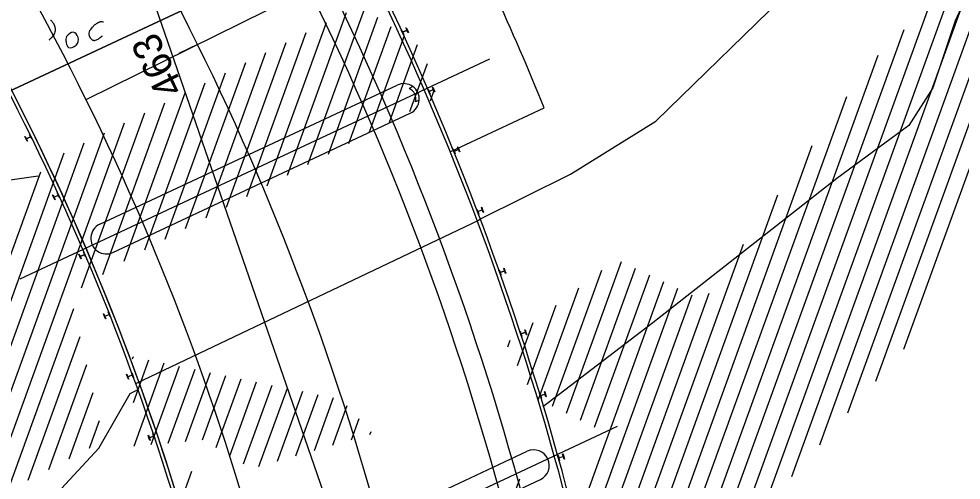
# Model space of a CAD drawing. Extents: x 2355002 to 2355569, y 708374 to 709566.
# Drawn here: x 2355318.9 to 2355409.8, y 709300.1 to 709344.6 of the extents above; entities that cross this region are included whole.
import ezdxf

# ---------------------------------------------------------------- set-up
doc = ezdxf.new("R2010")
doc.units = 0
for name, color, linetype in [('BD_X_Building', 7, 'Continuous'), ('BR_X_Brg_Centerline', 7, 'Continuous'), ('BR_X_Det_Centerline', 7, 'Continuous'), ('BR_X_Rail_Stl_Det', 7, 'Continuous'), ('BR_X_Slab_Object', 7, 'Continuous'), ('DR_X_Ditch', 7, 'Continuous'), ('HY_X_Water_Edge', 7, 'Continuous'), ('HY_X_Wetland_Area', 7, 'Continuous'), ('PM_X_CL_Double_Solid', 7, 'Continuous'), ('PM_X_Edge_Line', 7, 'Continuous'), ('PM_X_Stop_Line', 7, 'Continuous'), ('RD_X_RR_2', 7, 'Continuous'), ('RD_X_RR_Cells', 7, 'Continuous'), ('RD_X_Wall', 7, 'Continuous'), ('VG_X_Cells', 7, 'Continuous'), ('VG_X_Tree_Line_Rt', 7, 'Continuous')]:
    doc.layers.add(name, color=color, linetype=linetype)

msp = doc.modelspace()

# ---------------------------------------------------------------- linework, layer by layer
at = {"layer": 'BD_X_Building'}
msp.add_line((2355325.355, 709336.796), (2355346.875, 709347.42), dxfattribs=at)
msp.add_arc((2355104.75, 709227.886), 272.024, 5.4603, 29.69206, dxfattribs=at)
at = {"layer": 'BR_X_Brg_Centerline'}
for p, q in [((2355319.014, 709319.52), (2355364.3, 709340.715)), ((2355331.329, 709284.107), (2355376.615, 709305.301))]:
    msp.add_line(p, q, dxfattribs=at)
at = {"layer": 'BR_X_Det_Centerline'}
msp.add_line((2355360.141, 709264.65), (2355328.268, 709356.793), dxfattribs=at)
at = {"layer": 'BR_X_Rail_Stl_Det'}
for points in [[(2355356.299, 709343.513), (2355356.211, 709343.704), (2355356.245, 709343.72), (2355356.351, 709343.49)], [(2355355.921, 709343.244), (2355356.008, 709343.053), (2355355.974, 709343.037), (2355355.762, 709343.498), (2355355.797, 709343.514), (2355355.885, 709343.323)], [(2355355.924, 709343.308), (2355356.284, 709343.473)], [(2355356.295, 709343.449), (2355355.935, 709343.284)], [(2355356.351, 709343.49), (2355356.457, 709343.259), (2355356.423, 709343.244), (2355356.335, 709343.435)], [(2355358.465, 709337.535), (2355358.548, 709337.342), (2355358.514, 709337.327), (2355358.313, 709337.792), (2355358.347, 709337.807), (2355358.431, 709337.614)], [(2355358.47, 709337.598), (2355358.834, 709337.756)], [(2355358.844, 709337.731), (2355358.481, 709337.574)], [(2355358.849, 709337.795), (2355358.766, 709337.988), (2355358.801, 709338.003), (2355358.901, 709337.77)], [(2355358.901, 709337.77), (2355359.002, 709337.538), (2355358.967, 709337.523), (2355358.883, 709337.716)], [(2355319.573, 709332.995), (2355319.462, 709333.222), (2355319.496, 709333.239), (2355319.588, 709333.05)], [(2355319.626, 709332.973), (2355319.719, 709332.784), (2355319.685, 709332.767), (2355319.573, 709332.995)], [(2355319.628, 709333.037), (2355319.984, 709333.211)], [(2355319.996, 709333.187), (2355319.64, 709333.013)], [(2355319.998, 709333.251), (2355319.906, 709333.439), (2355319.94, 709333.456), (2355320.162, 709333.001), (2355320.128, 709332.984), (2355320.036, 709333.173)], [(2355360.88, 709331.769), (2355360.959, 709331.575), (2355360.924, 709331.56), (2355360.733, 709332.03), (2355360.768, 709332.044), (2355360.847, 709331.849)], [(2355360.886, 709331.833), (2355361.253, 709331.982)], [(2355361.263, 709331.957), (2355360.896, 709331.808)], [(2355361.27, 709332.021), (2355361.191, 709332.215), (2355361.226, 709332.23), (2355361.321, 709331.995)], [(2355361.321, 709331.995), (2355361.416, 709331.76), (2355361.381, 709331.746), (2355361.302, 709331.941)], [(2355322.241, 709327.358), (2355322.135, 709327.589), (2355322.17, 709327.604), (2355322.257, 709327.413)], [(2355322.293, 709327.335), (2355322.381, 709327.144), (2355322.346, 709327.128), (2355322.241, 709327.358)], [(2355322.297, 709327.398), (2355322.657, 709327.563)], [(2355322.668, 709327.539), (2355322.308, 709327.374)], [(2355322.672, 709327.603), (2355322.584, 709327.794), (2355322.619, 709327.81), (2355322.83, 709327.349), (2355322.795, 709327.333), (2355322.708, 709327.524)], [(2355363.56, 709326.194), (2355363.485, 709326.39), (2355363.521, 709326.403), (2355363.611, 709326.167)], [(2355363.164, 709325.951), (2355363.239, 709325.755), (2355363.203, 709325.741), (2355363.024, 709326.215), (2355363.059, 709326.228), (2355363.134, 709326.032)], [(2355363.172, 709326.014), (2355363.543, 709326.155)], [(2355363.552, 709326.13), (2355363.182, 709325.99)], [(2355363.611, 709326.167), (2355363.701, 709325.93), (2355363.665, 709325.916), (2355363.59, 709326.113)], [(2355324.76, 709321.654), (2355324.661, 709321.887), (2355324.696, 709321.902), (2355324.778, 709321.708)], [(2355324.817, 709321.693), (2355325.182, 709321.848)], [(2355325.192, 709321.823), (2355324.828, 709321.668)], [(2355325.198, 709321.887), (2355325.115, 709322.08), (2355325.15, 709322.095), (2355325.349, 709321.629), (2355325.314, 709321.614), (2355325.231, 709321.808)], [(2355324.812, 709321.629), (2355324.894, 709321.436), (2355324.86, 709321.421), (2355324.76, 709321.654)], [(2355365.315, 709320.082), (2355365.385, 709319.884), (2355365.349, 709319.871), (2355365.18, 709320.349), (2355365.216, 709320.361), (2355365.286, 709320.163)], [(2355365.324, 709320.145), (2355365.698, 709320.277)], [(2355365.707, 709320.252), (2355365.333, 709320.12)], [(2355365.716, 709320.315), (2355365.646, 709320.514), (2355365.681, 709320.526), (2355365.766, 709320.287)], [(2355365.766, 709320.287), (2355365.85, 709320.049), (2355365.815, 709320.036), (2355365.745, 709320.234)], [(2355327.573, 709316.108), (2355327.496, 709316.303), (2355327.531, 709316.317), (2355327.718, 709315.846), (2355327.683, 709315.832), (2355327.605, 709316.027)], [(2355327.13, 709315.886), (2355327.037, 709316.121), (2355327.072, 709316.135), (2355327.15, 709315.94)], [(2355327.181, 709315.86), (2355327.259, 709315.664), (2355327.223, 709315.65), (2355327.13, 709315.886)], [(2355327.188, 709315.923), (2355327.557, 709316.069)], [(2355327.567, 709316.044), (2355327.198, 709315.898)], [(2355367.333, 709314.166), (2355367.399, 709313.967), (2355367.363, 709313.955), (2355367.204, 709314.436), (2355367.24, 709314.448), (2355367.306, 709314.248)], [(2355367.739, 709314.391), (2355367.673, 709314.591), (2355367.709, 709314.603), (2355367.788, 709314.362)], [(2355367.344, 709314.229), (2355367.72, 709314.353)], [(2355367.728, 709314.328), (2355367.352, 709314.204)], [(2355367.788, 709314.362), (2355367.868, 709314.121), (2355367.832, 709314.11), (2355367.766, 709314.309)], [(2355329.349, 709310.058), (2355329.262, 709310.296), (2355329.298, 709310.309), (2355329.37, 709310.111)], [(2355329.399, 709310.03), (2355329.472, 709309.833), (2355329.436, 709309.82), (2355329.349, 709310.058)], [(2355329.408, 709310.094), (2355329.78, 709310.23)], [(2355329.789, 709310.205), (2355329.417, 709310.069)], [(2355329.798, 709310.268), (2355329.726, 709310.465), (2355329.761, 709310.478), (2355329.935, 709310.003), (2355329.9, 709309.99), (2355329.827, 709310.187)], [(2355369.218, 709308.206), (2355369.279, 709308.005), (2355369.242, 709307.994), (2355369.095, 709308.479), (2355369.131, 709308.49), (2355369.192, 709308.289)], [(2355369.23, 709308.269), (2355369.609, 709308.384)], [(2355369.617, 709308.358), (2355369.237, 709308.243)], [(2355369.629, 709308.421), (2355369.567, 709308.622), (2355369.604, 709308.633), (2355369.677, 709308.391)], [(2355369.677, 709308.391), (2355369.751, 709308.149), (2355369.715, 709308.138), (2355369.654, 709308.339)], [(2355331.869, 709304.372), (2355331.802, 709304.572), (2355331.838, 709304.584), (2355332, 709304.104), (2355331.964, 709304.092), (2355331.897, 709304.291)], [(2355331.415, 709304.174), (2355331.334, 709304.414), (2355331.37, 709304.426), (2355331.437, 709304.227)], [(2355331.465, 709304.145), (2355331.532, 709303.946), (2355331.496, 709303.934), (2355331.415, 709304.174)], [(2355331.475, 709304.208), (2355331.85, 709304.335)], [(2355331.859, 709304.309), (2355331.483, 709304.183)], [(2355371.382, 709302.411), (2355371.325, 709302.613), (2355371.362, 709302.623), (2355371.43, 709302.379)], [(2355370.966, 709302.205), (2355371.022, 709302.002), (2355370.986, 709301.992), (2355370.849, 709302.48), (2355370.886, 709302.49), (2355370.943, 709302.288)], [(2355370.979, 709302.267), (2355371.361, 709302.374)], [(2355371.368, 709302.348), (2355370.986, 709302.242)], [(2355371.43, 709302.379), (2355371.498, 709302.135), (2355371.461, 709302.125), (2355371.405, 709302.327)]]:
    msp.add_lwpolyline(points, dxfattribs=at)
for centre, radius, start, end in [((2355104.75, 709227.887), 276.024, 8.80517, 29.69195), ((2355104.75, 709227.887), 276.024, 8.80517, 29.69195), ((2355104.75, 709227.887), 276.357, 8.80517, 29.69195), ((2355104.75, 709227.887), 239.69, 6.23645, 29.69194), ((2355104.75, 709227.887), 240.024, 6.23645, 29.69194), ((2355355.912, 709343.335), 0.0298, 204.67725, 294.67725), ((2355355.948, 709343.257), 0.0298, 114.67725, 204.67725), ((2355356.272, 709343.501), 0.0298, 294.67725, 24.67725), ((2355356.308, 709343.422), 0.0298, 24.67725, 114.67725), ((2355358.458, 709337.626), 0.0298, 203.38147, 293.38147), ((2355358.492, 709337.547), 0.0298, 113.38147, 203.38147), ((2355358.822, 709337.783), 0.0298, 293.38147, 23.38147), ((2355358.856, 709337.704), 0.0298, 23.38147, 113.38147), ((2355319.615, 709333.063), 0.0298, 206.07139, 296.07139), ((2355319.653, 709332.986), 0.0298, 116.07139, 206.07139), ((2355319.971, 709333.237), 0.0298, 296.07139, 26.07139), ((2355320.009, 709333.16), 0.0298, 26.07139, 116.07139), ((2355360.875, 709331.86), 0.0298, 202.08568, 292.08568), ((2355360.907, 709331.781), 0.0298, 112.08568, 202.08568), ((2355361.242, 709332.009), 0.0298, 292.08568, 22.08568), ((2355361.274, 709331.93), 0.0298, 22.08568, 112.08568), ((2355322.284, 709327.426), 0.0298, 204.57738, 294.57738), ((2355322.32, 709327.347), 0.0298, 114.57738, 204.57738), ((2355322.645, 709327.59), 0.0298, 294.57738, 24.57738), ((2355322.681, 709327.512), 0.0298, 24.57738, 114.57738), ((2355363.162, 709326.042), 0.0298, 200.7899, 290.7899), ((2355363.192, 709325.962), 0.0298, 110.7899, 200.7899), ((2355363.532, 709326.183), 0.0298, 290.7899, 20.7899), ((2355363.563, 709326.102), 0.0298, 20.7899, 110.7899), ((2355324.806, 709321.72), 0.0298, 203.08337, 293.08337), ((2355325.17, 709321.875), 0.0298, 293.08337, 23.08337), ((2355325.204, 709321.796), 0.0298, 23.08337, 113.08337), ((2355324.839, 709321.641), 0.0298, 113.08337, 203.08337), ((2355365.314, 709320.173), 0.0298, 199.49411, 289.49411), ((2355365.343, 709320.092), 0.0298, 109.49411, 199.49411), ((2355365.688, 709320.305), 0.0298, 289.49411, 19.49411), ((2355365.716, 709320.224), 0.0298, 19.49411, 109.49411), ((2355327.177, 709315.951), 0.0298, 201.58937, 291.58937), ((2355327.209, 709315.871), 0.0298, 111.58937, 201.58937), ((2355327.546, 709316.097), 0.0298, 291.58937, 21.58937), ((2355327.577, 709316.016), 0.0298, 21.58937, 111.58937), ((2355367.334, 709314.257), 0.0298, 198.28804, 288.28804), ((2355367.361, 709314.175), 0.0298, 108.28804, 198.28804), ((2355367.711, 709314.382), 0.0298, 288.28804, 18.28804), ((2355367.738, 709314.3), 0.0298, 18.28804, 108.28804), ((2355329.398, 709310.122), 0.0298, 200.09536, 290.09536), ((2355329.427, 709310.041), 0.0298, 110.09536, 200.09536), ((2355329.77, 709310.258), 0.0298, 290.09536, 20.09536), ((2355329.799, 709310.177), 0.0298, 20.09536, 110.09536), ((2355369.221, 709308.297), 0.0298, 196.90255, 286.90255), ((2355369.246, 709308.215), 0.0298, 106.90255, 196.90255), ((2355369.6, 709308.412), 0.0298, 286.90255, 16.90255), ((2355369.625, 709308.33), 0.0298, 16.90255, 106.90255), ((2355331.465, 709304.237), 0.0298, 198.60135, 288.60135), ((2355331.493, 709304.155), 0.0298, 108.60135, 198.60135), ((2355331.841, 709304.363), 0.0298, 288.60135, 18.60135), ((2355331.868, 709304.281), 0.0298, 18.60135, 108.60135), ((2355370.971, 709302.296), 0.0298, 195.60676, 285.60676), ((2355370.994, 709302.213), 0.0298, 105.60676, 195.60676), ((2355371.353, 709302.403), 0.0298, 285.60676, 15.60676), ((2355371.376, 709302.319), 0.0298, 15.60676, 105.60676)]:
    msp.add_arc(centre, radius, start, end, dxfattribs=at)
at = {"layer": 'BR_X_Slab_Object'}
msp.add_arc((2355104.75, 709227.887), 240.024, 6.69347, 29.69206, dxfattribs=at)
at = {"layer": 'DR_X_Ditch'}
msp.add_lwpolyline([(2355256.934, 709256.527), (2355268.599, 709283.201), (2355275.266, 709297.997), (2355281.566, 709308.847), (2355288.953, 709317.469), (2355300.165, 709325.51), (2355311.07, 709328.057), (2355320.733, 709329.426)], dxfattribs=at)
at = {"layer": 'HY_X_Water_Edge'}
for points in [[(2355363.282, 709325.224), (2355372.076, 709329.606), (2355380.301, 709334.699), (2355393.648, 709347.722), (2355403.056, 709358.394), (2355409.122, 709369.207), (2355415.073, 709376.309), (2355426.464, 709387.971), (2355433.074, 709392.925), (2355443.129, 709397.915)], [(2355457.32, 709385.786), (2355441.013, 709378.943), (2355433.104, 709372.961), (2355421.777, 709364.094), (2355413.483, 709353.728), (2355409.195, 709344.375), (2355407.043, 709337.933), (2355404.726, 709334.3), (2355397.78, 709329.181), (2355380.013, 709315.254), (2355370.996, 709308.366), (2355369.41, 709307.158)], [(2355250.911, 709219.998), (2355253.586, 709233.349), (2355257.951, 709241.6), (2355265.075, 709252.406), (2355277.693, 709262.077), (2355294.163, 709271.671), (2355304.717, 709276.5), (2355308.101, 709280.351), (2355314.576, 709287.749), (2355320.15, 709296.253), (2355326.599, 709303.193), (2355329.602, 709308.443), (2355330.306, 709308.794)]]:
    msp.add_lwpolyline(points, dxfattribs=at)
at = {"layer": 'HY_X_Wetland_Area'}
msp.add_line((2355330.152, 709309.405), (2355363.296, 709325.185), dxfattribs=at)
msp.add_lwpolyline([(2355402.731, 709358.025), (2355392.727, 709358.151), (2355360.724, 709357.63), (2355311.362, 709334.527), (2355296.582, 709319.103), (2355283.234, 709303.179), (2355271.55, 709272.489), (2355265.075, 709252.406)], dxfattribs=at)
at = {"layer": 'PM_X_CL_Double_Solid'}
msp.add_arc((2355104.75, 709227.886), 258.024, 5.4603, 29.69206, dxfattribs=at)
msp.add_arc((2355104.75, 709227.886), 258.024, 5.4603, 29.69206, dxfattribs=at)
at = {"layer": 'PM_X_Edge_Line'}
for radius in [270.024, 246.024]:
    msp.add_arc((2355104.75, 709227.886), radius, 5.4603, 29.69206, dxfattribs=at)
at = {"layer": 'PM_X_Stop_Line'}
msp.add_lwpolyline([(2355306.276, 709345.396), (2355290.879, 709324.489), (2355296.582, 709319.103), (2355311.362, 709334.527), (2355360.724, 709357.63), (2355392.727, 709358.151), (2355391.331, 709364.068), (2355355.637, 709368.498)], dxfattribs=at)
for points in [[(2355321.933, 709344.461), (2355321.994, 709344.407), (2355322.05, 709344.348), (2355322.15, 709344.219), (2355322.234, 709344.079), (2355322.27, 709344.006), (2355322.286, 709343.97), (2355322.301, 709343.933), (2355322.324, 709343.872), (2355322.342, 709343.809), (2355322.367, 709343.68), (2355322.365, 709343.413), (2355322.222, 709343.018), (2355322.181, 709342.955), (2355322.134, 709342.895), (2355322.045, 709342.791), (2355321.955, 709342.694), (2355321.863, 709342.604), (2355321.769, 709342.52)], [(2355325.724, 709343.438), (2355326.071, 709343.876), (2355326.177, 709343.985), (2355326.3, 709344.078), (2355326.433, 709344.159), (2355326.5, 709344.197), (2355326.567, 709344.235), (2355326.592, 709344.249), (2355326.618, 709344.262), (2355326.673, 709344.284), (2355326.79, 709344.313), (2355326.965, 709344.295), (2355327.018, 709344.267), (2355327.024, 709344.263)], [(2355323.478, 709342.865), (2355324.122, 709343.29), (2355324.589, 709342.783), (2355324.404, 709342.047), (2355323.656, 709341.822), (2355323.452, 709342.269), (2355323.419, 709342.614), (2355323.478, 709342.865)], [(2355326.91, 709342.911), (2355326.867, 709342.874), (2355326.822, 709342.837), (2355326.776, 709342.8), (2355326.728, 709342.763), (2355326.651, 709342.705), (2355326.571, 709342.648), (2355326.407, 709342.548), (2355326.243, 709342.484), (2355326.163, 709342.471), (2355326.124, 709342.471), (2355326.105, 709342.473), (2355326.096, 709342.474), (2355326.086, 709342.475), (2355326.061, 709342.481), (2355326.037, 709342.489), (2355325.989, 709342.513), (2355325.899, 709342.586), (2355325.818, 709342.683), (2355325.781, 709342.737), (2355325.764, 709342.765), (2355325.756, 709342.779), (2355325.748, 709342.793), (2355325.721, 709342.844), (2355325.699, 709342.895), (2355325.67, 709342.997), (2355325.66, 709343.098), (2355325.663, 709343.149), (2355325.672, 709343.2), (2355325.724, 709343.438)]]:
    msp.add_spline(points, degree=3, dxfattribs=at)
at = {"layer": 'RD_X_RR_2'}
for p, q in [((2355356.879, 709338.043), (2355356.517, 709337.874)), ((2355357.494, 709336.728), (2355357.132, 709336.559))]:
    msp.add_line(p, q, dxfattribs=at)
for radius, start, end in [(1.167, 346.58594, 63.57556), (1.5, 356.12573, 54.03578)]:
    msp.add_arc((2355355.998, 709336.829), radius, start, end, dxfattribs=at)
at = {"layer": 'RD_X_RR_Cells'}
for p, q in [((2355401.543, 709309.65), (2355416.829, 709351.833)), ((2355404.25, 709312.716), (2355418.648, 709352.45)), ((2355398.837, 709306.584), (2355415.01, 709351.216)), ((2355393.423, 709300.452), (2355411.372, 709349.983)), ((2355396.13, 709303.518), (2355413.191, 709350.599)), ((2355390.717, 709297.386), (2355409.264, 709348.567)), ((2355346.763, 709330.517), (2355352.231, 709345.606)), ((2355388.847, 709296.629), (2355406.762, 709346.065)), ((2355344.796, 709329.491), (2355350.484, 709345.187)), ((2355348.73, 709331.543), (2355353.508, 709344.727)), ((2355342.829, 709328.465), (2355348.538, 709344.22)), ((2355350.698, 709332.569), (2355354.784, 709343.847)), ((2355387.007, 709295.952), (2355404.26, 709343.564)), ((2355340.861, 709327.439), (2355346.592, 709343.253)), ((2355352.665, 709333.595), (2355356.061, 709342.967)), ((2355338.894, 709326.413), (2355344.646, 709342.286)), ((2355354.632, 709334.621), (2355357.338, 709342.088)), ((2355336.927, 709325.387), (2355342.7, 709341.318)), ((2355385.166, 709295.275), (2355401.758, 709341.063)), ((2355334.96, 709324.361), (2355340.754, 709340.351)), ((2355356.599, 709335.647), (2355358.275, 709340.272)), ((2355332.992, 709323.335), (2355338.808, 709339.384)), ((2355331.025, 709322.309), (2355336.862, 709338.417)), ((2355329.031, 709321.21), (2355334.916, 709337.45)), ((2355358.567, 709336.673), (2355358.934, 709337.688)), ((2355326.968, 709319.92), (2355332.97, 709336.483)), ((2355383.325, 709294.598), (2355398.725, 709337.095)), ((2355324.906, 709318.63), (2355331.024, 709335.516)), ((2355315.854, 709298.054), (2355329.079, 709334.549)), ((2355313.888, 709297.031), (2355327.133, 709333.581)), ((2355311.922, 709296.008), (2355325.187, 709332.614)), ((2355381.484, 709293.921), (2355395.409, 709332.349)), ((2355309.983, 709295.062), (2355323.241, 709331.647)), ((2355308.395, 709295.082), (2355320.989, 709329.837)), ((2355379.644, 709293.244), (2355392.094, 709327.603)), ((2355377.803, 709292.567), (2355388.779, 709322.857)), ((2355371.707, 709306.565), (2355377.004, 709321.182)), ((2355370.357, 709307.242), (2355375.099, 709320.328)), ((2355373.057, 709305.887), (2355378.366, 709320.538)), ((2355374.407, 709305.209), (2355379.728, 709319.894)), ((2355371.867, 709293.798), (2355381.09, 709319.25)), ((2355369.007, 709307.92), (2355372.894, 709318.646)), ((2355372.28, 709290.537), (2355382.452, 709318.606)), ((2355375.962, 709291.89), (2355385.464, 709318.111)), ((2355374.121, 709291.213), (2355383.814, 709317.962)), ((2355317.82, 709299.077), (2355324.186, 709316.645)), ((2355367.922, 709309.329), (2355370.689, 709316.964)), ((2355366.982, 709311.137), (2355368.484, 709315.282)), ((2355319.786, 709300.101), (2355324.803, 709313.944)), ((2355366.042, 709312.945), (2355366.279, 709313.6)), ((2355329.85, 709311.794), (2355329.926, 709312.004)), ((2355321.753, 709301.124), (2355325.42, 709311.243)), ((2355329.92, 709307.585), (2355331.411, 709311.7)), ((2355329.99, 709303.375), (2355332.897, 709311.396)), ((2355331.64, 709303.526), (2355334.382, 709311.092)), ((2355333.29, 709303.677), (2355335.867, 709310.788)), ((2355334.94, 709303.828), (2355337.353, 709310.484)), ((2355336.591, 709303.979), (2355338.838, 709310.18)), ((2355337.919, 709303.242), (2355340.323, 709309.876)), ((2355339.229, 709302.454), (2355341.809, 709309.572)), ((2355340.539, 709301.666), (2355343.294, 709309.268)), ((2355323.719, 709302.147), (2355326.036, 709308.542)), ((2355342.038, 709301.4), (2355344.779, 709308.965)), ((2355343.821, 709301.917), (2355346.264, 709308.661)), ((2355345.604, 709302.434), (2355347.75, 709308.357)), ((2355347.386, 709302.951), (2355349.235, 709308.053)), ((2355349.169, 709303.468), (2355350.551, 709307.282)), ((2355325.685, 709303.17), (2355326.653, 709305.842)), ((2355350.952, 709303.986), (2355351.697, 709306.042)), ((2355352.735, 709304.503), (2355352.844, 709304.803)), ((2355324.203, 709269.639), (2355335.553, 709300.961)), ((2355362.36, 709286.882), (2355367.192, 709300.215))]:
    msp.add_line(p, q, dxfattribs=at)
at = {"layer": 'RD_X_Wall'}
msp.add_line((2355336.115, 709342.108), (2355334.322, 709341.222), dxfattribs=at)
msp.add_arc((2355104.75, 709227.886), 258.024, 5.4603, 29.69206, dxfattribs=at)
at = {"layer": 'VG_X_Cells'}
for p, q in [((2355326.681, 709324.764), (2355355.362, 709338.188)), ((2355327.953, 709322.047), (2355356.633, 709335.471)), ((2355338.769, 709289.245), (2355367.903, 709302.88)), ((2355340.041, 709286.528), (2355369.175, 709300.163))]:
    msp.add_line(p, q, dxfattribs=at)
for centre, start, end in [((2355355.998, 709336.829), 54.03578, 115.08075), ((2355355.998, 709336.829), 295.08075, 356.12573), ((2355327.317, 709323.406), 115.08075, 295.08075), ((2355368.539, 709301.522), 295.08075, 115.08075)]:
    msp.add_arc(centre, 1.5, start, end, dxfattribs=at)
at = {"layer": 'VG_X_Tree_Line_Rt'}
msp.add_line((2355360.486, 709331.753), (2355369.555, 709335.998), dxfattribs=at)
msp.add_arc((2355104.75, 709227.887), 286.024, 22.2085, 27.0676, dxfattribs=at)

# ---------------------------------------------------------------- texts
at = {"layer": 'DR_X_Ditch'}
msp.add_text('X', height=0.14, rotation=25.08075, dxfattribs=at).set_placement((2355360.82, 709331.714))
at = {"layer": 'RD_X_Wall'}
msp.add_text('463', height=2.8, rotation=116.27488, dxfattribs=at).set_placement((2355334.873, 709337.846))

doc.saveas('drawing.dxf')
